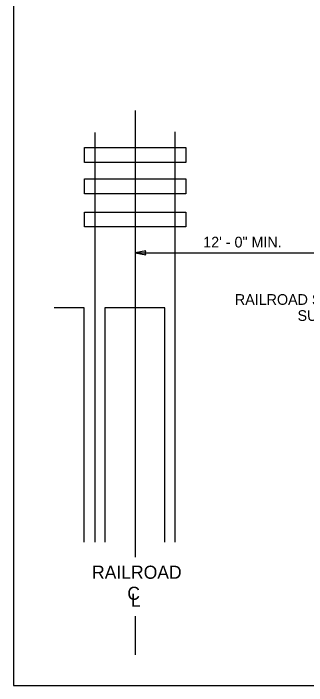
# Model space of a CAD drawing. Extents: x 99862 to 103680, y 99470 to 102076.
# Drawn here: x 99862 to 100301, y 100000 to 101005 of the extents above; entities that cross this region are included whole.
import ezdxf

# ---------------------------------------------------------------- set-up
doc = ezdxf.new("R2010")
doc.units = 0
for name, color, linetype in [('Level 1', 7, 'Continuous'), ('Level 13', 7, 'Continuous'), ('Level 15', 7, 'Continuous'), ('Level 20', 7, 'Continuous'), ('Level 60', 7, 'Continuous')]:
    doc.layers.add(name, color=color, linetype=linetype)

msp = doc.modelspace()

# ---------------------------------------------------------------- linework, layer by layer
at = {"layer": 'Level 1'}
msp.add_lwpolyline([(99862, 99999.5), (103151, 99999.5), (103151, 102075.5), (99862, 102075.5)], close=True, dxfattribs=at)
at = {"layer": 'Level 13'}
for p, q in [((99984.3, 100213.8), (99984.3, 100826.5)), ((100104.3, 100627.7), (100104.3, 100827.8)), ((100104.3, 100213.8), (100104.3, 100627.7)), ((99967.8, 100564.2), (99923, 100564.2)), ((99967.8, 100213.8), (99967.8, 100564.2)), ((100088.5, 100564.2), (99998.9, 100564.2)), ((99998.9, 100564.2), (99998.9, 100213.8)), ((100088.5, 100213.8), (100088.5, 100564.2))]:
    msp.add_line(p, q, dxfattribs=at)
for points in [[(99968.4, 100804.2), (100120.2, 100804.2), (100120.2, 100782), (99968.4, 100782)], [(99968.4, 100757.2), (100120.2, 100757.2), (100120.2, 100734.9), (99968.4, 100734.9)], [(99968.4, 100707.7), (100120.2, 100707.7), (100120.2, 100685.4), (99968.4, 100685.4)]]:
    msp.add_lwpolyline(points, close=True, dxfattribs=at)
at = {"layer": 'Level 15'}
for p, q in [((100044.4, 100859.8), (100044.4, 100191.4)), ((100044.4, 100646.7), (100332.4, 100646.7)), ((100044.4, 100103.2), (100044.4, 100045.5))]:
    msp.add_line(p, q, dxfattribs=at)
msp.add_lwpolyline([(100044.4, 100646.7), (100060.1, 100643.6), (100059.4, 100646.7), (100060.1, 100649.7)], close=True, dxfattribs=at)
at = {"layer": 'Level 60'}
msp.add_line((99862, 99999.5), (99862, 99999.5), dxfattribs=at)

# ---------------------------------------------------------------- texts
at = {"layer": 'Level 13'}
for s, height, p in [('RAILROAD', 19.62, (99979.7, 100159.2)), ('C', 19.6, (100032.5, 100127.7)), ('L', 19.6, (100038, 100117.4))]:
    msp.add_text(s, height=height, dxfattribs=at).set_placement(p)
at = {"layer": 'Level 20'}
for s, p in [('12\' - 0" MIN.', (100146.1, 100654.7)), ('RAILROAD SIGNAL', (100193.5, 100568.9)), ('SUPPORT', (100287.3, 100544.9))]:
    msp.add_text(s, height=16, dxfattribs=at).set_placement(p)

doc.saveas('drawing.dxf')
